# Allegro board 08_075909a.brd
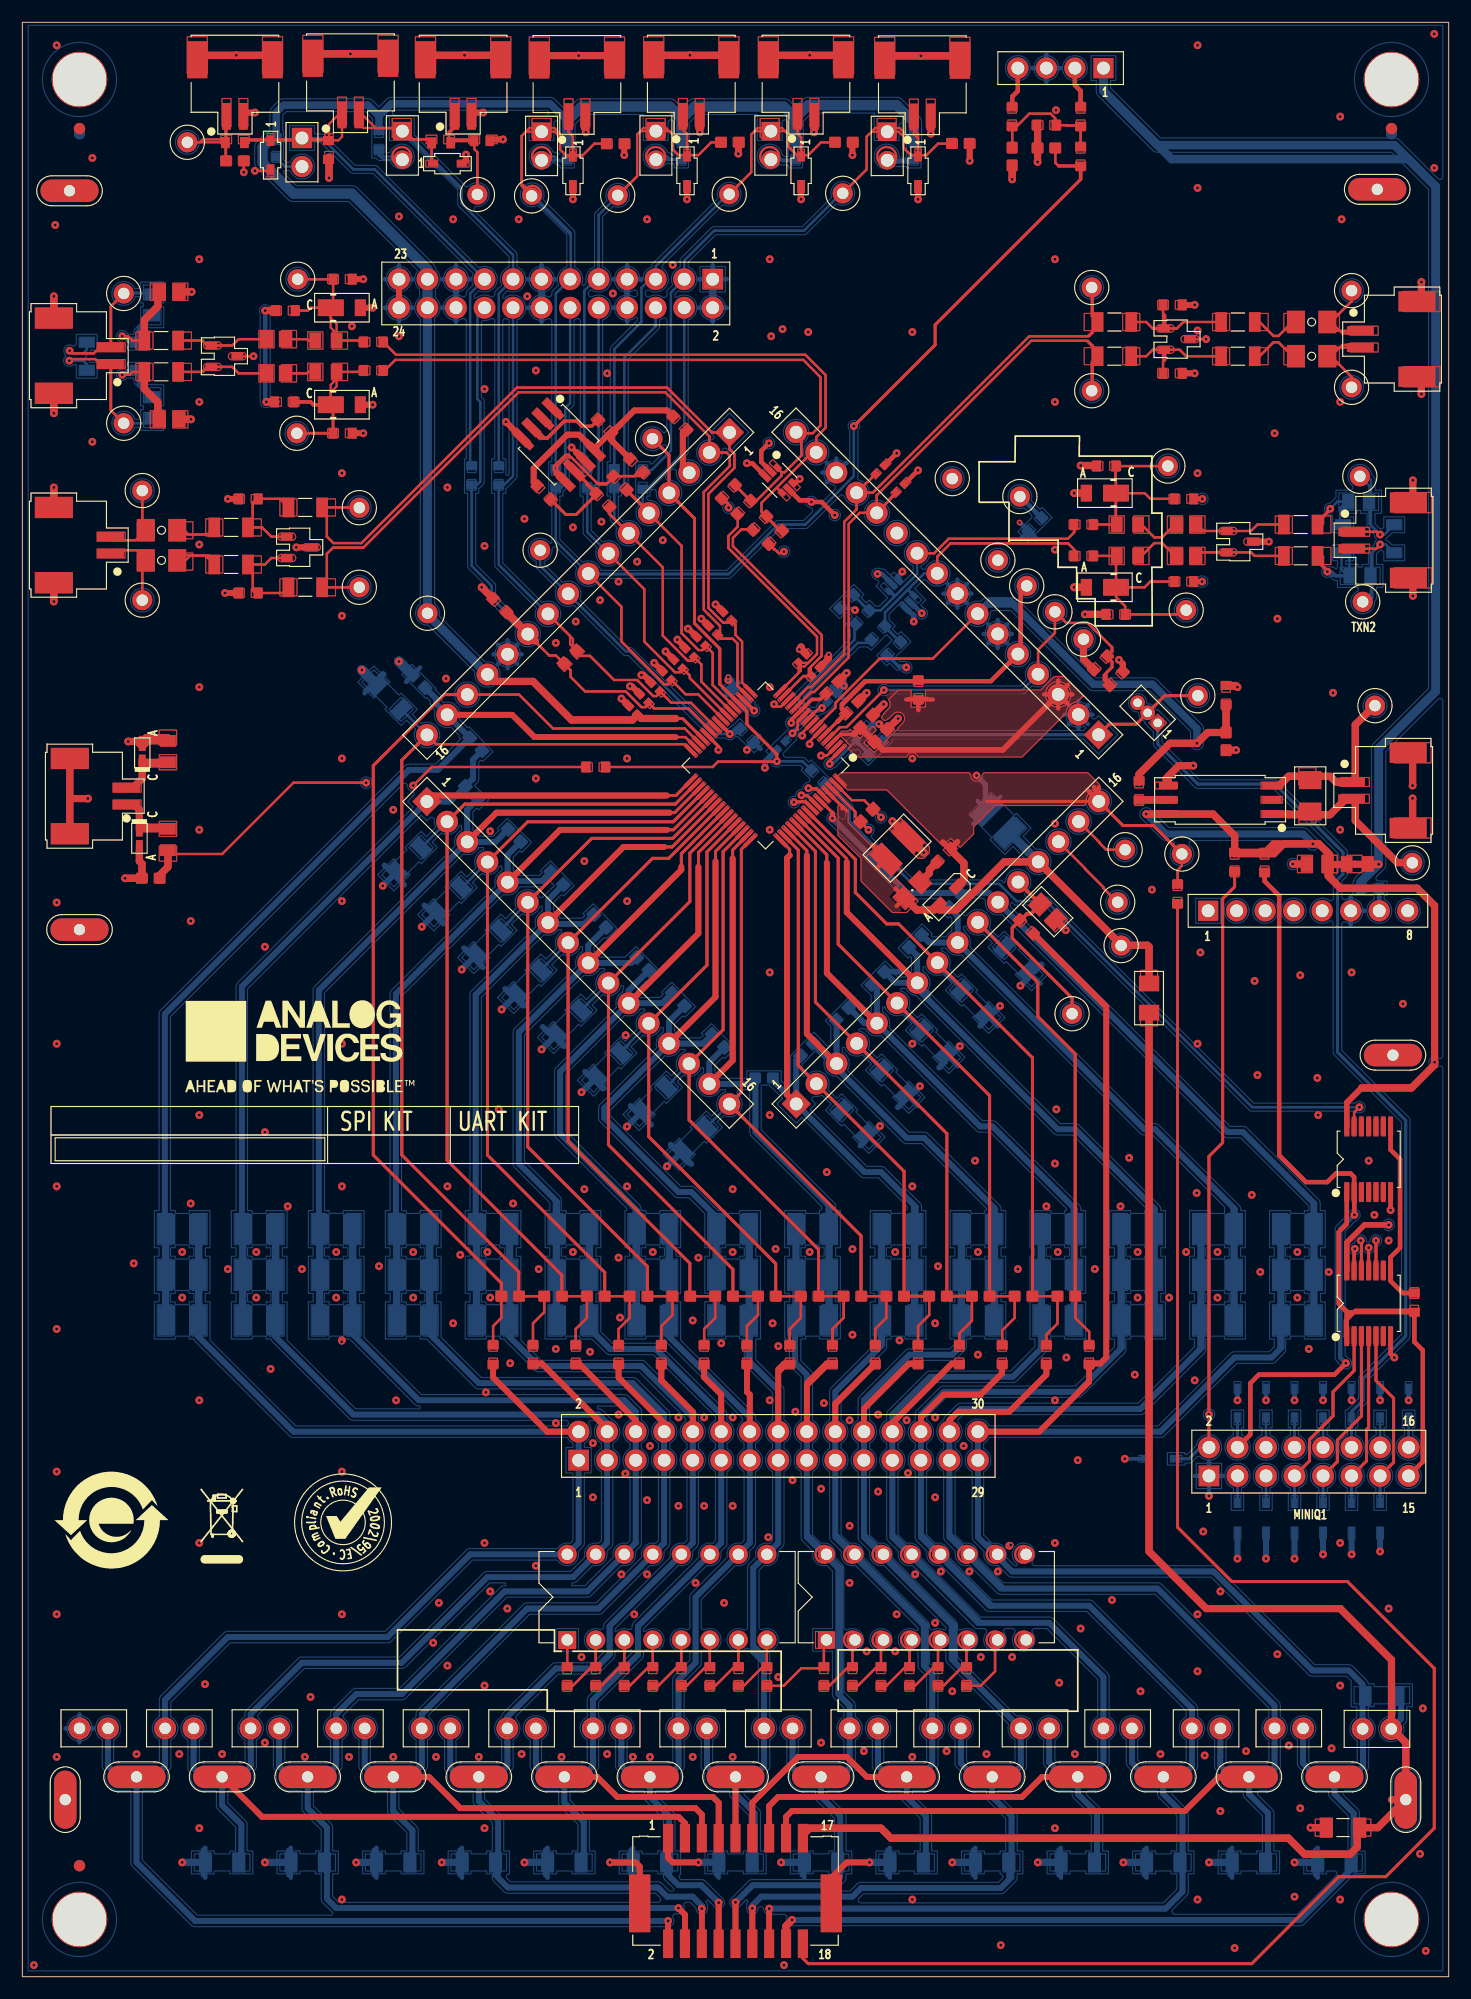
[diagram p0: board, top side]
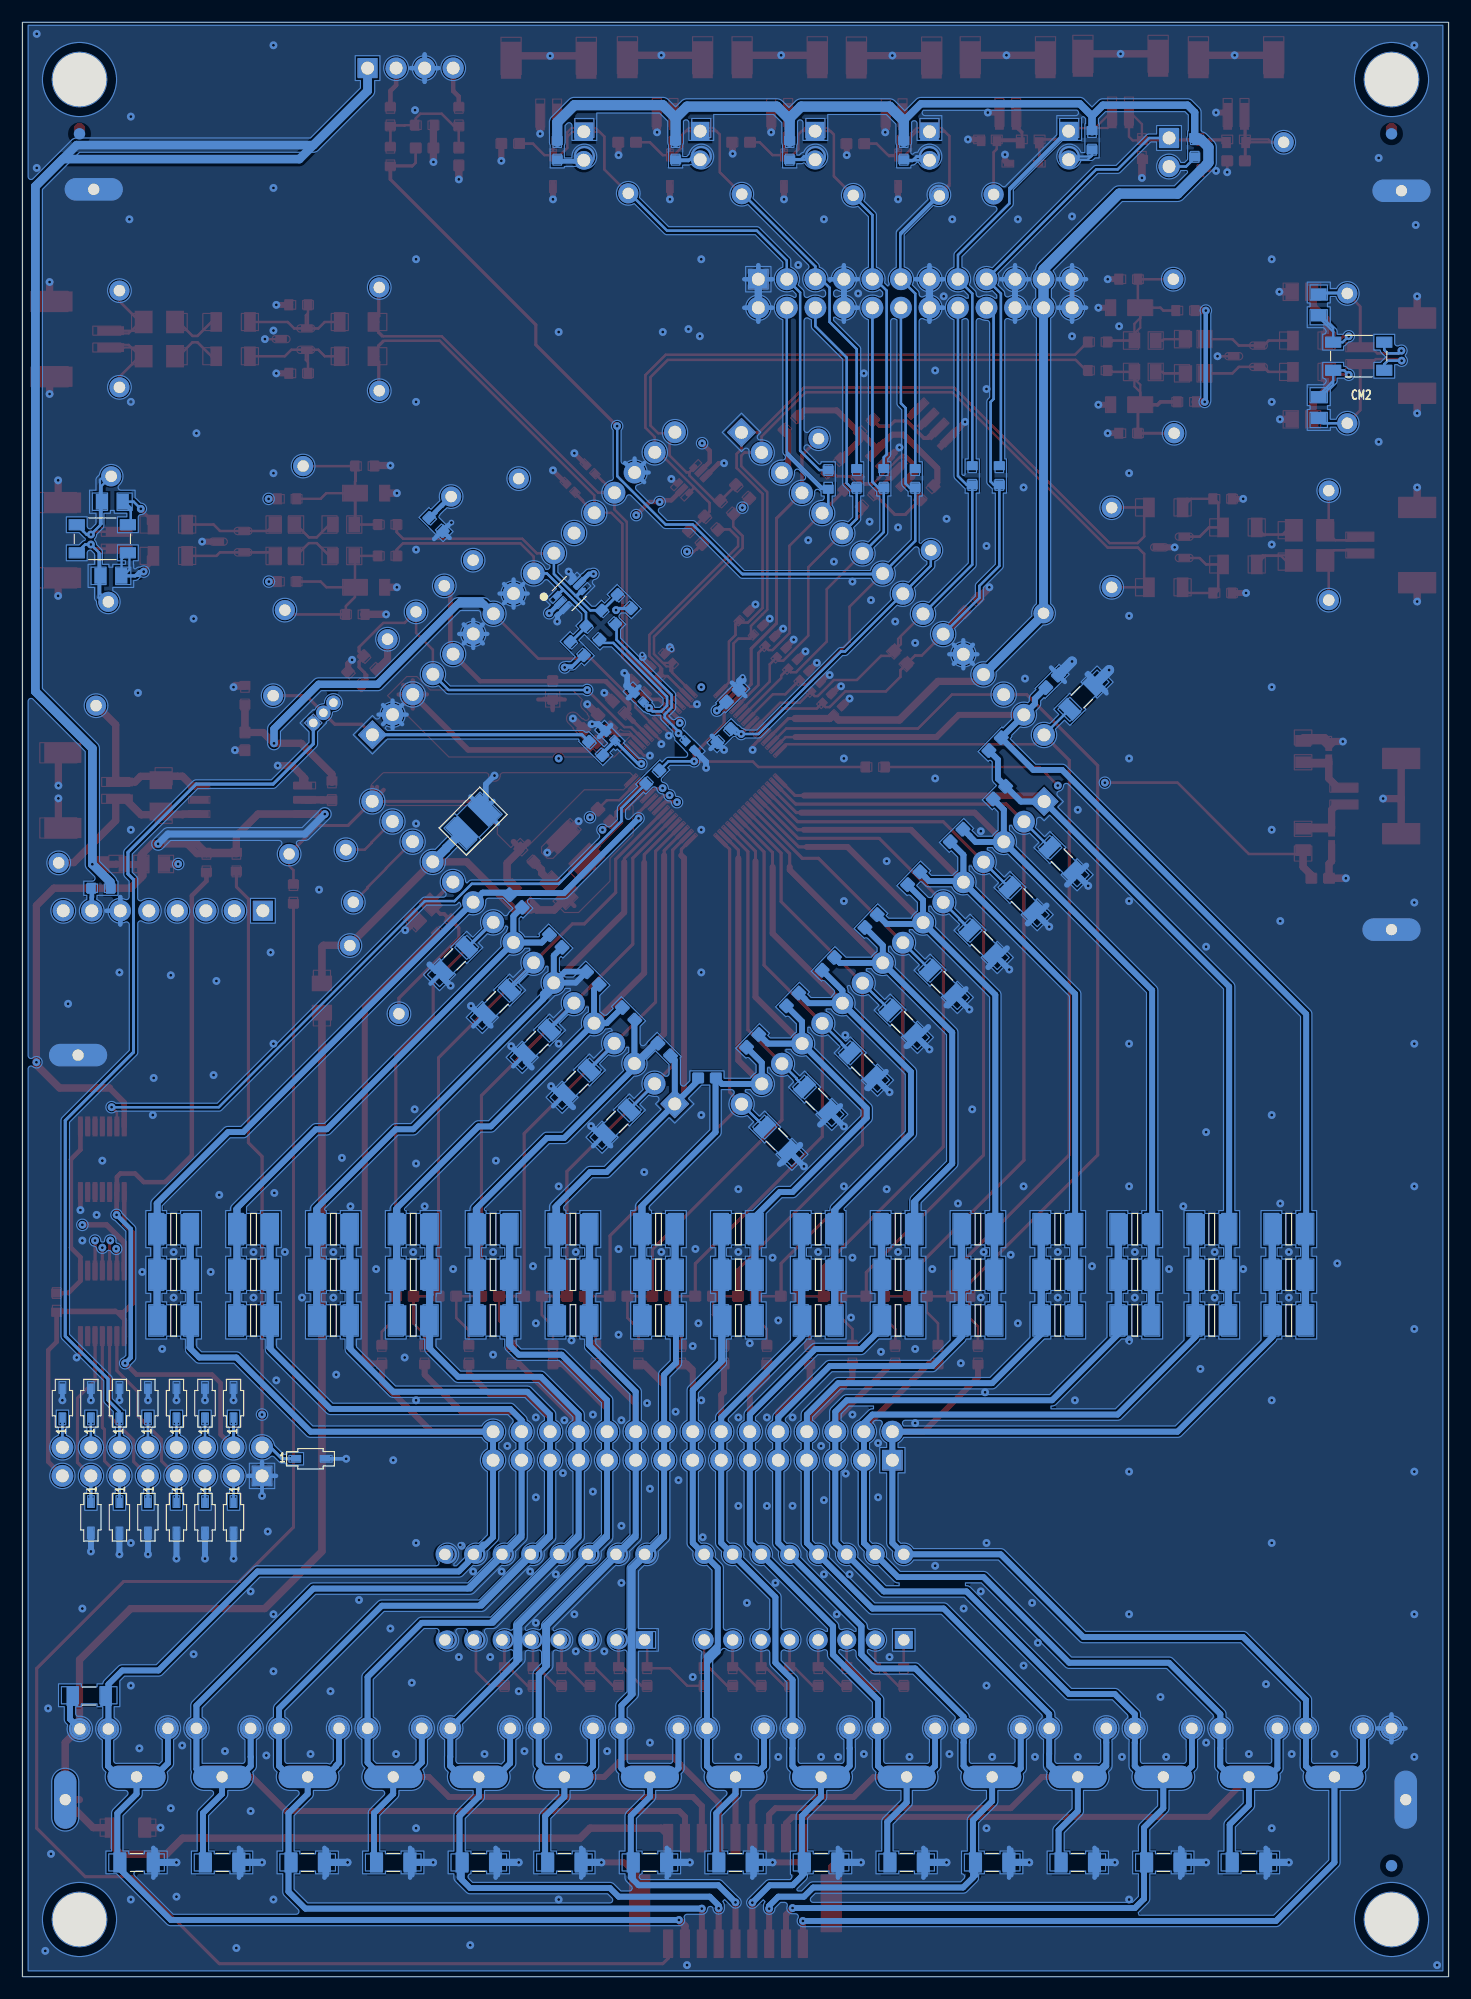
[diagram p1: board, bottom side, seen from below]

Outline 127 x 173.99 mm; copper layers: TOP, L2_GND, L3_GND, BOTTOM. Coordinates in mm from the lower left corner of the outline.
Outline path: 0,173.99 0,0 127,0 127,173.99 0,173.99

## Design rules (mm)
constraint set DEFAULT: min track width 0.203

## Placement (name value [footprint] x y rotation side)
ALARM_IN_UP  502584-0270  [CNMOLEX502584-0270]  122.15 105.61 270 top
ALARM_OUT_LP  502584-0270  [CNMOLEX502584-0270]  5.47 105.1 90 top
ALERTIN  RED  [CNKEY5001TP]  86.87 126.11 0 top
ALERTIN_N  RED  [CNKEY5001TP]  120.45 113.16 0 top
ALERTIN_P  RED  [CNKEY5001TP]  123.77 99.16 0 top
ALERTOUT  RED  [CNKEY5001TP]  56.11 136.93 0 top
AUXGND  YEL  [CNKEY5001TP]  46.1 127 0 top
B0P-  PEC02SAAN  [CNSULLINSPEC02SAAN]  5.08 22.1 0 top
B1B0  PEC02SAAN  [CNSULLINSPEC02SAAN]  12.7 22.1 0 top
B2B1  PEC02SAAN  [CNSULLINSPEC02SAAN]  20.32 22.1 0 top
B3B2  PEC02SAAN  [CNSULLINSPEC02SAAN]  27.94 22.1 0 top
B4B3  PEC02SAAN  [CNSULLINSPEC02SAAN]  35.56 22.1 0 top
B5B4  PEC02SAAN  [CNSULLINSPEC02SAAN]  43.18 22.1 0 top
B6B5  PEC02SAAN  [CNSULLINSPEC02SAAN]  50.8 22.1 0 top
B7B6  PEC02SAAN  [CNSULLINSPEC02SAAN]  58.42 22.1 0 top
B8B7  PEC02SAAN  [CNSULLINSPEC02SAAN]  66.04 22.1 0 top
B9B8  PEC02SAAN  [CNSULLINSPEC02SAAN]  73.66 22.1 0 top
B10B9  PEC02SAAN  [CNSULLINSPEC02SAAN]  81.03 22.1 0 top
B11B10  PEC02SAAN  [CNSULLINSPEC02SAAN]  88.9 22.1 0 top
B12B11  PEC02SAAN  [CNSULLINSPEC02SAAN]  96.27 22.1 0 top
B13B12  PEC02SAAN  [CNSULLINSPEC02SAAN]  104.14 22.1 0 top
B14B13  PEC02SAAN  [CNSULLINSPEC02SAAN]  111.51 22.1 0 top
BAT0  9020  [CNWEICO9020]  10.16 17.78 0 top
BAT1  9020  [CNWEICO9020]  17.78 17.78 0 top
BAT2  9020  [CNWEICO9020]  25.4 17.78 0 top
BAT3  9020  [CNWEICO9020]  33.02 17.78 0 top
BAT4  9020  [CNWEICO9020]  40.64 17.78 0 top
BAT5  9020  [CNWEICO9020]  48.26 17.78 0 top
BAT6  9020  [CNWEICO9020]  55.88 17.78 0 top
BAT7  9020  [CNWEICO9020]  63.5 17.78 0 top
BAT8  9020  [CNWEICO9020]  71.12 17.78 0 top
BAT9  9020  [CNWEICO9020]  78.74 17.78 0 top
BAT10  9020  [CNWEICO9020]  86.36 17.78 0 top
BAT11  9020  [CNWEICO9020]  93.98 17.78 0 top
BAT12  9020  [CNWEICO9020]  101.6 17.78 0 top
BAT13  9020  [CNWEICO9020]  109.22 17.78 0 top
BAT14  9020  [CNWEICO9020]  116.84 17.78 0 top
C1  0.1UF  [C0603#2]  75.18 103.38 45 top
C2  1000pF  [C0402]  74.6 110.41 45 bottom
C3  1UF  [C0603#2]  75.18 111.75 45 top
C4  0.47uF  [C0603]  73.85 112.97 45 top
C5  0.47uF  [C0603]  72.07 114.75 45 top
C6  4.7uF  [C0805H60]  79.25 96.72 45 top
C7  0.47uF  [C0603#2]  63.75 114.05 135 bottom
C8  0.01uF  [C0402]  60.45 118.87 135 top
C9  0.01uF  [C0402]  59.44 117.86 135 top
C10  0.01uF  [C0402]  58.42 116.84 135 top
C11  0.01uF  [C0402]  57.4 115.82 135 top
C12  0.01uF  [C0402]  56.39 114.81 135 top
C13  0.01uF  [C0402]  55.37 113.79 135 top
C14  100pF  [C0402]  54.43 112.7 135 top
C15  3900pF  [C0603#2]  76.45 110.48 45 top
C16  0.47uF  [C0603#2]  91.19 162.81 180 top
C17  0.01uF  [C0603#2]  88.14 162.05 270 top
C18  2.2UF  [C1210H95]  77.89 100.47 45 top
C19  2.2UF  [C1210H95]  86.87 102.87 135 bottom
C20  0.1uF  [C1206]  88.49 90.58 315 bottom
C21  0.47uF  [C0805H53]  91.3 94.82 315 top
C22  0.1uF  [C1206]  84.68 86.77 315 bottom
C23  0.1uF  [C1206]  81.13 83.21 315 bottom
C24  0.1uF  [C1206]  77.57 79.65 315 bottom
C25  0.1uF  [C1206]  74.02 76.1 315 bottom
C26  0.1uF  [C1206]  59.84 74.57 225 bottom
C27  0.1uF  [C1206]  56.29 78.13 225 bottom
C28  0.1uF  [C1206]  52.22 81.18 225 bottom
C29  0.1uF  [C1206]  48.67 84.99 225 bottom
C30  0.1uF  [C1206]  45.11 88.54 225 bottom
C31  0.1uF  [C1206]  41.55 92.1 225 bottom
C32  0.1uF  [C1206]  38 95.91 225 bottom
C33  0.1uF  [C1206]  34.44 99.47 225 bottom
C34  0.1uF  [C1206]  116.84 10.16 0 bottom
C35  0.1uF  [C1206]  109.22 10.16 0 bottom
C36  0.1uF  [C1206]  101.6 10.16 0 bottom
C37  0.1uF  [C1206]  93.98 10.16 0 bottom
C38  0.1uF  [C1206]  86.36 10.16 0 bottom
C39  0.1uF  [C1206]  78.74 10.16 0 bottom
C40  0.1uF  [C1206]  71.12 10.16 0 bottom
C41  0.1uF  [C1206]  63.5 10.16 0 bottom
C42  0.1uF  [C1206]  55.88 10.16 0 bottom
C43  0.1uF  [C1206]  48.26 10.16 0 bottom
C44  0.1uF  [C1206]  40.64 10.16 0 bottom
C45  0.1uF  [C1206]  33.02 10.16 0 bottom
C46  0.1uF  [C1206]  25.4 10.16 0 bottom
C47  0.1uF  [C1206]  17.78 10.16 0 bottom
C48  0.1uF  [C0603#2]  92.98 60.58 180 top
C49  0.1uF  [C0603#2]  89.14 60.58 180 top
C50  0.1uF  [C0603#2]  85.33 60.58 180 top
C51  0.1uF  [C0603#2]  81.52 60.58 180 top
C52  0.1uF  [C0603#2]  77.71 60.58 180 top
C53  0.1uF  [C0603#2]  73.93 60.58 180 top
C54  0.1uF  [C0603#2]  70.12 60.58 180 top
C55  0.1uF  [C0603#2]  66.31 60.58 180 top
C56  0.1uF  [C0603#2]  62.5 60.58 180 top
C57  0.1uF  [C0603#2]  58.69 60.58 180 top
C58  0.1uF  [C0603#2]  54.88 60.58 180 top
C59  0.1uF  [C0603#2]  51.07 60.58 180 top
C60  0.1uF  [C0603#2]  47.26 60.58 180 top
C61  0.1uF  [C0603#2]  43.43 60.58 180 top
C62  0.1uF  [C0603#2]  83.07 95.77 225 bottom
C63  0.1uF  [C0603#2]  79.51 92.21 225 bottom
C64  0.1uF  [C0603#2]  76.21 88.91 225 bottom
C65  0.1uF  [C0603#2]  73.02 85.72 225 bottom
C66  0.1uF  [C0603#2]  69.84 82.54 225.1 bottom
C67  0.1uF  [C0603#2]  66.03 80.01 180 bottom
C68  0.1uF  [C0603#2]  61.97 83.32 133.8 bottom
C69  0.1uF  [C0603#2]  58.41 87 134 bottom
C70  0.1uF  [C0603#2]  55.24 90.18 133.9 bottom
C71  0.1uF  [C0603#2]  51.43 93.99 133.7 bottom
C72  0.1uF  [C0603#2]  47.62 97.8 133.8 bottom
C73  0.1uF  [C0603#2]  43.81 101.61 135.4 bottom
C74  0.1uF  [C0603#2]  40 105.42 134.8 bottom
C75  0.1uF  [C0603#2]  40.38 109.74 134 bottom
C76  15pF  [C0402]  72.06 113.84 45 bottom
C77  18pF  [C0402]  78.15 132.51 45 top
C78  15pF  [C0402]  70.63 116.15 45 top
C79  15pF  [C0402]  67.56 109.6 225 bottom
C80  18pF  [C0402]  61.55 119.81 135 top
C81  18pF  [C0402]  76.38 134.16 45 top
C82  15pF  [C0402]  69.47 117.35 45 top
C83  18pF  [C0402]  62.82 121.08 135 top
C84  0.1uF  [C1206]  32.66 113.89 135 bottom
C85  1UF  [C0603#2]  35.3 115.32 135 bottom
C86  0.01uF  [C0603#2]  48.77 117.49 225 top
C87  39PF  [C0603#2]  107.19 109.97 270 top
C88  100pF  [C1206H37]  114.68 105.13 270 top
C89  2200PF  [C1206H71]  12.38 126.09 0 top
C90  2200PF  [C1206H71]  12.38 128.78 0 top
C91  2200PF  [C1206H71]  114.81 144.27 0 top
C92  2200PF  [C1206H71]  114.81 147.32 0 top
C93  15pF  [C0603#2]  11.42 97.79 180 top
C100  0.1uF  [C1206]  117.6 13.26 180 top
C101  100pF  [C0805]  13.06 138.65 0 top
C102  100pF  [C0805]  13.06 150.01 180 top
C104  0.01uF  [C0603#2]  18.92 161.67 0 top
C105  0.01uF  [C0603#2]  52.81 163.19 0 top
C106  0.01uF  [C0603#2]  83.54 163.22 0 top
C107  0.01uF  [C0603#2]  73.15 163.32 0 top
C108  0.01uF  [C0603#2]  63.02 163.32 0 top
C109  0.01uF  [C0603]  40.92 163.42 0 top
CM1  2800 OHMS  [FL1812]  119.89 128.02 180 bottom
CM2  2800 OHMS  [FL1812]  8 144.28 0 bottom
CPN  RED  [CNKEY5001TP]  97.54 95.66 0 top
CPP  RED  [CNKEY5001TP]  98.2 100.33 0 top
CURRENTSENSE  502584-0270  [CNMOLEX502584-0270]  29.21 169.54 0 top
D3  SP4021-01FTG  [SOD323_B]  22.1 162.18 270 top
D4  SP4021-01FTG  [SOD323_B]  37.85 161.42 0 top
D5  SP4021-01FTG  [SOD323_B]  79.76 160.78 270 top
D6  SP4021-01FTG  [SOD323_B]  69.34 160.78 270 top
D7  SP4021-01FTG  [SOD323_B]  59.18 160.78 270 top
D8  SP4021-01FTG  [SOD323_B]  49.02 160.78 270 top
D9  PESD3V3U1UB,115  [SOD523H26]  10.41 101.35 270 top
D10  PESD3V3U1UB,115  [SOD523H26]  10.67 108.97 90 top
D11  SP4021-01FTG  [SOD323_B]  120.9 40.89 270 bottom
D12  SP4021-01FTG  [SOD323_B]  118.36 40.89 270 bottom
D13  SP4021-01FTG  [SOD323_B]  115.82 40.89 270 bottom
D14  SP4021-01FTG  [SOD323_B]  113.28 40.89 270 bottom
D15  SP4021-01FTG  [SOD323_B]  110.74 40.89 270 bottom
D16  SP4021-01FTG  [SOD323_B]  108.2 40.89 270 bottom
D18  SP4021-01FTG  [SOD323_B]  123.44 51.05 90 bottom
D19  SP4021-01FTG  [SOD323_B]  120.9 51.05 90 bottom
D20  SP4021-01FTG  [SOD323_B]  118.36 51.05 90 bottom
D21  SP4021-01FTG  [SOD323_B]  115.82 51.05 90 bottom
D22  SP4021-01FTG  [SOD323_B]  113.28 51.05 90 bottom
D23  SP4021-01FTG  [SOD323_B]  110.74 51.05 90 bottom
D24  SP4021-01FTG  [SOD323_B]  108.2 51.05 90 bottom
D25  SP4021-01FTG  [SOD323_B]  101.35 46.1 180 bottom
D26  DFLS1100-7  [POWERDI123]  96.39 132.08 180 top
D28  DFLS1100-7  [POWERDI123]  28.45 148.59 0 top
D29  SESDONCAN1LT1G  [SOT23_B]  102.82 145.8 270 top
D30  DFLS1100-7  [POWERDI123]  96.39 123.7 180 top
D31  DFLS1100-7  [POWERDI123]  28.45 139.95 0 top
D32  SESDONCAN1LT1G  [SOT23_B]  24.69 127.26 270 top
D33  SESDONCAN1LT1G  [SOT23_B]  108.41 127.76 270 top
D34  SESDONCAN1LT1G  [SOT23_B]  17.98 144.27 270 top
D40  BAT20J  [SOD323]  82.42 96.24 225 top
DCIN  RED  [CNKEY5001TP]  97.84 91.8 0 top
GND_A  9020  [CNWEICO9020]  5.08 93.22 0 top
GND_A1  9020  [CNWEICO9020]  122.05 82.04 0 top
GND_A2  9020  [CNWEICO9020]  4.19 159 0 top
GND_A3  9020  [CNWEICO9020]  120.65 159.13 0 top
GP/AUX0  BLK  [CNKEY5001TP]  73.05 158.78 0 top
GP/AUX1  BLK  [CNKEY5001TP]  62.94 158.7 0 top
GP/AUX2  BLK  [CNKEY5001TP]  53.01 158.6 0 top
GP/AUX3  BLK  [CNKEY5001TP]  45.34 158.55 0 top
GP/AUX4  BLK  [CNKEY5001TP]  40.51 158.67 0 top
GP/AUX5  BLK  [CNKEY5001TP]  14.68 163.32 0 top
GPIO_AUX0  502584-0270  [CNMOLEX502584-0270]  80.14 169.37 0 top
GPIO_AUX1  502584-0270  [CNMOLEX502584-0270]  69.77 169.42 0 top
GPIO_AUX2  502584-0270  [CNMOLEX502584-0270]  59.56 169.42 0 top
GPIO_AUX3  502584-0270  [CNMOLEX502584-0270]  49.38 169.39 0 top
GPIO_AUX4  502584-0270  [CNMOLEX502584-0270]  39.24 169.42 0 top
GPIO_AUX5  502584-0270  [CNMOLEX502584-0270]  18.92 169.42 0 top
HV  RED  [CNKEY5001TP]  103.25 99.95 0 top
J1  TSW-116-07-G-S  [CNHDR1X16H335]  95.83 110.57 135 top
J2  TSW-116-07-G-S  [CNHDR1X16H335]  62.97 137.49 225 top
J3  TSW-116-07-G-S  [CNHDR1X16H335]  36.02 104.62 315 top
J4  TSW-116-07-G-S  [CNHDR1X16H335]  68.91 77.7 45 top
J5  PEC12DAAN  [CNTHMHDR2X12L1200W200H343]  61.47 151.13 180 top
J6  PBC15DAAN  [CNTHMHDR2X15L1500W200H330]  49.53 45.97 0 top
J7  5031541890  [CNMOLEX5031541890]  63.5 7.62 180 top
J8  SSW-104-01-G-S  [CNSAMTECSSW-104-XX-X-S]  96.27 169.93 180 top
L1  600OHM AT 100MEGHZ  [L0805]  103.63 126.49 180 top
L2  600OHM AT 100MEGHZ  [L0805]  103.63 129.29 180 top
L3  600OHM AT 100MEGHZ  [L0805]  22.58 142.75 0 top
L4  600OHM AT 100MEGHZ  [L0805]  22.58 145.8 0 top
MINIQ1  PEC08DAAN  [CNTHMHDR2X8L800W200H343_OE]  105.66 44.58 0 top
MINIQ2  SSW-108-01-G-S  [CNSAMTECSSW-108-01-G-S]  105.59 94.89 0 top
NOREF  -  []  24.13 82.8 0 top
NOREF#2  -  []  64.49 194.18 0 top
NOREF#3  -  []  127 0 90 top
NOREF#4  -  [unnamed#2]  5.08 9.87 0 top
NOREF#5  -  []  -181.84 -111.94 0 top
NOREF#6  -  []  215.65 186.06 0 top
NOREF#7  -  []  28.55 40.44 0 top
NOREF#8  -  []  127 173.99 180 top
NOREF#9  -  []  2.67 21.89 0 top
NOREF#10  -  []  0 173.99 270 top
NOREF#11  -  []  0 173.99 0 top
NOREF#12  -  []  127 0 0 top
NOREF#13  -  []  127 0 90 top
NOREF#14  -  []  2.54 74.42 0 top
NOREF#15  -  []  0 0 0 top
NOREF#16  -  []  0 173.99 0 top
NOREF#17  -  [unnamed#2]  121.92 164.54 0 top
NOREF#18  -  []  0 0 0 top
NOREF#19  -  []  -74.4 -30.86 0 top
NOREF#20  -  []  0 0 0 top
NOREF#21  -  []  91.64 33.95 0 top
NOREF#22  -  []  -183.21 -111.58 0 top
NOREF#23  -  []  0 0 0 top
NOREF#24  -  []  146.91 316.51 0 top
NOREF#25  -  []  124.3 169.11 0 top
NOREF#26  -  []  0 0 0 top
NOREF#27  -  []  123.72 22 0 top
NOREF#28  -  [unnamed#2]  5.08 164.54 0 top
NOREF#29  -  []  17.55 36.83 0 top
NOREF#30  -  []  7.92 40.64 0 top
NOREF#31  -  [unnamed#2]  5.08 9.87 180 bottom
NOREF#32  -  [unnamed#2]  121.92 5.08 180 bottom
NOREF#33  -  [unnamed#2]  5.08 164.08 180 bottom
NOREF#34  -  [unnamed#2]  121.92 164.08 180 bottom
NOREF#35  -  [unnamed#2]  5.08 168.91 180 bottom
NOREF#36  -  [unnamed#2]  5.08 5.08 180 bottom
NOREF#37  -  [unnamed#2]  121.92 168.91 180 bottom
OPTO_OUT  YEL  [CNKEY5001TP]  88.82 131.78 0 top
P+B14  PEC02SAAN  [CNSULLINSPEC02SAAN]  119.35 22.05 0 top
PACK+  9020  [CNWEICO9020]  123.19 15.75 90 top
PACK-  9020  [CNWEICO9020]  3.81 15.75 90 top
Q1  BC857BS-7-F  [SOT363-3]  67.44 133.22 225 top
Q2  BC857BS-7-F  [SOT363-3]  78.31 123.14 225 bottom
R1  0  [R0603]  73.41 122.43 45 bottom
R2  0  [R0603]  62.87 132.21 45 top
R3  0  [R0603]  77.6 118.24 45 bottom
R4  0  [R0603]  67.06 128.14 45 top
R5  0  [R0603]  76.2 119.63 225 bottom
R6  0  [R0603]  74.8 121.03 225 bottom
R7  0  [R0603]  65.66 129.41 225 top
R8  0  [R0603]  64.26 130.81 225 top
R9  10K  [R0603]  96.01 116.97 225 top
R10  10K  [R0603]  97.41 115.57 225 top
R11  0  [R0603]  79.78 114.55 90 top
R12  100K  [R0603]  90.17 129.29 45 bottom
R13  0  [R0603]  94.49 129.29 180 top
R14  0  [R0603]  31.24 143 0 top
R15  0  [R0603]  94.49 126.49 180 top
R16  0  [R0603]  31.24 145.54 0 top
R17  100  [R1206-2]  100.33 87.12 90 top
R18  1.02K  [R0603]  89.41 93.47 135 top
R19  10  [R0603]  82.09 99.87 45 top
R20  0  [R0805]  11.56 139.7 90 bottom
R21  22  [R1210]  113.54 62.48 0 bottom
R22  100K  [R0603]  75.95 109.35 45 bottom
R23  0  [R0603]  102.87 96.39 90 top
R24  0  [R0603]  120.02 96.9 180 bottom
R25  22  [R1210]  106.43 66.55 0 bottom
R26  0  [R0603]  58.55 138.3 315 top
R27  0  [R0805]  11.56 148.84 270 bottom
R28  0  [R0603]  64.52 110.49 315 bottom
R29  22  [R1210]  99.31 66.55 0 bottom
R30  0  [R0603]  42.5 122.09 315 top
R31  0  [R0603]  27.25 162.64 270 top
R32  0  [R0805]  115.32 99.06 0 top
R33  22  [R1210]  92.2 66.55 0 bottom
R34  0  [R0805]  118.87 99.06 0 top
R35  22  [R1210]  113.54 66.55 0 bottom
R36  22  [R1210]  106.43 62.48 0 bottom
R37  22  [R1210]  85.09 66.55 0 bottom
R38  22  [R1210]  99.31 62.48 0 bottom
R39  22  [R1210]  92.2 62.48 0 bottom
R40  22  [R1210]  85.09 62.48 0 bottom
R41  22  [R1210]  77.98 66.55 0 bottom
R42  22  [R1210]  77.98 62.48 0 bottom
R43  22  [R1210]  70.36 66.55 0 bottom
R44  22  [R1210]  63.25 66.55 180 bottom
R45  22  [R1210]  70.36 62.48 0 bottom
R46  22  [R1210]  56.13 66.55 180 bottom
R47  22  [R1210]  49.02 66.55 180 bottom
R48  22  [R1210]  41.91 66.55 180 bottom
R49  22  [R1210]  63.25 62.48 180 bottom
R50  22  [R1210]  34.8 66.55 180 bottom
R51  22  [R1210]  27.94 66.55 180 bottom
R52  22  [R1210]  21.08 66.55 180 bottom
R53  22  [R1210]  56.13 62.48 180 bottom
R54  22  [R1210]  14.22 62.48 180 bottom
R55  22  [R1210]  99.31 58.42 0 bottom
R56  22  [R1210]  113.54 58.42 0 bottom
R57  22  [R1210]  49.02 62.48 180 bottom
R58  22  [R1210]  106.43 58.42 0 bottom
R59  22  [R1210]  92.2 58.42 0 bottom
R60  22  [R1210]  85.09 58.42 0 bottom
R61  22  [R1210]  41.91 62.48 180 bottom
R62  22  [R1210]  70.36 58.42 0 bottom
R63  22  [R1210]  63.25 58.42 180 bottom
R64  22  [R1210]  49.02 58.42 180 bottom
R65  22  [R1210]  34.8 62.48 180 bottom
R66  22  [R1210]  41.91 58.42 180 bottom
R67  22  [R1210]  34.8 58.42 180 bottom
R68  22  [R1210]  27.94 58.42 180 bottom
R69  22  [R1210]  27.94 62.48 180 bottom
R70  22  [R1210]  21.08 58.42 180 bottom
R71  22  [R1210]  77.98 58.42 0 bottom
R72  22  [R1210]  56.13 58.42 180 bottom
R73  22  [R1210]  21.08 62.48 180 bottom
R74  22  [R1210]  14.22 58.42 180 bottom
R77  22  [R1210]  14.22 66.55 180 bottom
R81  1K  [R0603]  49.28 55.37 90 top
R82  1K  [R0603]  45.47 55.37 90 top
R83  1K  [R0603]  41.91 55.37 90 top
R84  1K  [R0603]  64.52 55.37 90 top
R85  1K  [R0603]  60.71 55.37 90 top
R86  1K  [R0603]  56.9 55.37 90 top
R87  1K  [R0603]  53.09 55.37 90 top
R88  1K  [R0603]  72.14 55.37 90 top
R89  1K  [R0603]  68.33 55.37 90 top
R90  1K  [R0603]  75.95 55.37 90 top
R91  1K  [R0603]  95 55.37 90 top
R92  1K  [R0603]  91.19 55.37 90 top
R93  1K  [R0603]  87.25 55.37 90 top
R94  1K  [R0603]  83.44 55.37 90 top
R95  1K  [R0603]  79.76 55.37 90 top
R96  2K  [R0603]  84.07 26.73 90 top
R97  2K  [R0603]  81.53 26.73 90 top
R98  2K  [R0603]  78.99 26.73 90 top
R99  2K  [R0603]  76.45 26.73 90 top
R100  2K  [R0603]  73.91 26.73 90 top
R101  2K  [R0603]  71.37 26.73 90 top
R102  2K  [R0603]  66.29 26.73 90 top
R103  2K  [R0603]  63.75 26.73 90 top
R104  2K  [R0603]  61.21 26.73 90 top
R105  2K  [R0603]  58.67 26.73 90 top
R106  2K  [R0603]  56.13 26.73 90 top
R107  2K  [R0603]  53.59 26.73 90 top
R108  2K  [R0603]  51.05 26.73 90 top
R109  2K  [R0603]  48.51 26.73 90 top
R110  100K  [R0603]  107.19 114.11 90 top
R111  360  [R0805]  12.95 101.24 270 top
R112  360  [R0805]  12.95 109.07 90 top
R113  1K  [R0603]  99.44 105.6 90 top
R114  10K  [R0603]  107.95 99.25 270 top
R115  10K  [R0603]  46.44 132.12 315 top
R116  1K  [R0603]  55.24 133.29 270 bottom
R117  1K  [R0603]  52.7 133.41 270 bottom
R118  1K  [R0603]  47.5 133.41 270 bottom
R119  1K  [R0603]  42.42 133.67 270 bottom
R120  1K  [R0603]  40.01 133.67 270 bottom
R121  1K  [R0603]  50.29 133.41 270 bottom
R122  10K  [R0603]  79.38 162.62 270 bottom
R123  10K  [R0603]  68.83 162.62 270 bottom
R124  10K  [R0603]  58.67 162.62 270 bottom
R125  10K  [R0603]  51.86 138 135 top
R126  10K  [R0603]  48.51 162.62 270 bottom
R127  10K  [R0603]  31.75 163.51 270 bottom
R128  10K  [R0603]  22.61 162.88 270 bottom
R129  0  [R1206]  97.24 144.27 180 top
R130  0  [R1206]  97.24 147.32 180 top
R131  10K  [R0603]  54.69 134.54 315 top
R132  10K  [R0603]  123.95 60.01 90 top
R133  10K  [R0603]  103.44 124.21 180 top
R134  10K  [R0603]  97.35 121.28 180 top
R136  0  [R0603]  51.05 107.7 0 top
R137  15K  [R0603]  94.23 162.05 90 top
R138  0  [R1206]  25.19 123.7 0 top
R139  15K  [R0603]  91.19 164.85 180 top
R140  0  [R1206]  25.19 130.81 0 top
R141  0  [R0603]  70.87 106.81 315 bottom
R142  10K  [R0603]  110.62 99.19 270 top
R143  0  [R0603]  51.69 131.44 135 top
R144  0  [R0603]  94.23 165.61 90 top
R145  0  [R0603]  88.14 165.61 90 top
R146  10K  [R0603]  103.44 131.57 180 top
R147  10K  [R0603]  96.52 134.49 180 top
R148  0  [R0603]  53.21 132.97 315 top
R150  10K  [R0603]  28.51 137.41 0 top
R151  10K  [R0603]  23.31 140.21 0 top
R152  10K  [R0603]  28.51 151.13 0 top
R154  10K  [R0603]  23.43 148.34 0 top
R155  100K  [R0603]  102.42 142.75 0 top
R157  49.9  [R0805]  27.03 142.88 0 top
R158  49.9  [R0805]  98.4 126.49 180 top
R159  49.9  [R0805]  98.4 129.29 180 top
R160  49.9  [R0805]  27.03 145.67 0 top
R161  100K  [R0603]  102.42 148.84 0 top
R162  1.5K  [R1206]  108.24 144.27 180 top
R164  1.5K  [R1206]  108.24 147.32 180 top
R168  100K  [R0603]  20.13 123.19 180 top
R169  100K  [R0603]  20.13 131.57 180 top
R172  1.5K  [R1206]  18.58 125.73 0 top
R173  1.5K  [R1206]  18.58 129.03 0 top
R179  0  [R1206]  113.83 126.49 180 top
R180  0  [R1206]  113.83 129.29 180 top
R181  0  [R1206]  12.36 142.88 0 top
R182  0  [R1206]  12.36 145.67 0 top
R183  0  [R0805]  119.13 124.71 180 bottom
R184  0  [R0805]  119 131.32 180 bottom
R185  0  [R0603]  37.29 163.27 180 top
R186  0  [R0603]  18.92 163.3 0 top
R187  0  [R1206]  121.06 24.97 180 bottom
RXLN  RED  [CNKEY5001TP]  30 123.7 0 top
RXLP  RED  [CNKEY5001TP]  30 130.78 0 top
RXLP_CONN  502584-0270  [CNMOLEX502584-0270]  4.05 127.46 90 top
RXN1  BLK  [CNKEY5001TP]  10.67 122.56 0 top
RXN2  BLK  [CNKEY5001TP]  118.36 141.5 0 top
RXP1  RED  [CNKEY5001TP]  10.67 132.31 0 top
RXP2  RED  [CNKEY5001TP]  118.36 150.11 0 top
RXUN  RED  [CNKEY5001TP]  95.22 141.2 0 top
RXUP  RED  [CNKEY5001TP]  95.22 150.39 0 top
RXUP_CONN  502584-0270  [CNMOLEX502584-0270]  122.94 145.8 270 top
SHDNL  YEL  [CNKEY5001TP]  104.67 114.05 0 top
SHDNL_SEL  FTS-103-01-F-S  [CN1X3H159]  101.1 111.62 135 top
SW1  ADE0804  [SWDIP16]  71.6 29.97 0 top
SW2  ADE0804  [SWDIP16]  48.51 29.97 0 top
THERM  YEL  [CNKEY5001TP]  36.07 121.39 0 top
THERM1  3-644456-2  [CNHDR1X2H408]  77.01 164.26 270 top
THERM2  3-644456-2  [CNHDR1X2H408]  66.65 164.31 270 top
THERM3  3-644456-2  [CNHDR1X2H408]  56.41 164.31 270 top
THERM4  3-644456-2  [CNHDR1X2H408]  46.23 164.26 270 top
THERM5  3-644456-2  [CNHDR1X2H408]  33.83 164.31 270 top
THERM6  3-644456-2  [CNHDR1X2H408]  24.89 163.7 270 top
TXLN  RED  [CNKEY5001TP]  24.43 137.41 0 top
TXLP  RED  [CNKEY5001TP]  24.51 151.13 0 top
TXLP_CONN  502584-0270  [CNMOLEX502584-0270]  4.05 144.32 90 top
TXN1  BLK  [CNKEY5001TP]  9.02 138.3 0 top
TXN2  BLK  [CNKEY5001TP]  119.35 122.4 0 top
TXP1  RED  [CNKEY5001TP]  9.02 149.86 0 top
TXP2  RED  [CNKEY5001TP]  119.1 133.58 0 top
TXUN  RED  [CNKEY5001TP]  103.63 121.67 0 top
TXUP  RED  [CNKEY5001TP]  102.01 134.49 0 top
TXUP_CONN  502584-0270  [CNMOLEX502584-0270]  122.17 127.89 270 top
U1  ADES1754GCB/V+  [QFP64_10X10]  66.17 107.83 135 top
U2  MAX3378EEUD+  [TSSOP14]  119.89 59.94 0 top
U3  AT24CS08-SSHM-T  [SO8]  47.75 136.4 225 top
U4  MAX3390EEUD+  [TSSOP14]  119.89 72.77 0 top
U5  TLP2770(TP,E  [SO6_3_84X7_5]  106.66 104.78 90 top
UARTSEL  RED  [CNKEY5001TP]  91.95 121.51 0 top
VAA  RED  [CNKEY5001TP]  94.49 119.08 0 top
VBLK  RED  [CNKEY5001TP]  93.47 85.72 0 top
VDDL1  YEL  [CNKEY5001TP]  89.43 123.83 0 top
VDDL2/3  YEL  [CNKEY5001TP]  82.8 133.38 0 top

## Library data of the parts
ALARM_IN_UP ALARM_OUT_LP CURRENTSENSE GPIO_AUX0-GPIO_AUX5 RXLP_CONN RXUP_CONN TXLP_CONN TXUP_CONN = CN2P_2GND: User Part Number: UPN; Tolerance: N/A; alternate symbols: (CNMOLEX502584-0270); part number: CN2P_2GND_SM-502584-0270,E061613,CNMOLEX502584-0270; tolerance: N/A
ALERTIN ALERTIN_N ALERTIN_P ALERTOUT CPN CPP DCIN HV RXLN RXLP RXP1 RXP2 RXUN RXUP TXLN TXLP TXP1 TXP2 TXUN TXUP UARTSEL VAA VBLK = CNTP1P: Tolerance: N/A; User Part Number: UPN; alternate symbols: (CNKEY5001TP); part number: CNTP1P_TH-RED,E016323,CNKEY5001TP; tolerance: N/A
AUXGND OPTO_OUT SHDNL THERM VDDL1 VDDL2/3 = CNTP1P: Tolerance: N/A; User Part Number: UPN; alternate symbols: (CNKEY5001TP); part number: CNTP1P_TH-YEL,E016321,CNKEY5001TP; tolerance: N/A
B0P- B1B0 B2B1 B3B2 B4B3 B5B4 B6B5 B7B6 B8B7 B9B8 B10B9 B11B10 B12B11 B13B12 B14B13 P+B14 = CN2P: Tolerance: N/A; User Part Number: UPN; alternate symbols: (CNSULLINSPEC02SAAN); part number: CN2P_TH-PEC02SAAN,E011286,CNSULLINSPEC02SAAN; tolerance: N/A
BAT0-BAT14 GND_A GND_A1-GND_A3 PACK+ PACK- = CN1P: User Part Number: UPN; Tolerance: N/A; alternate symbols: (CNWEICO9020); part number: CN1P_TH-9020,E062254,CNWEICO9020; tolerance: N/A
C1 = CAP: User Part Number: UPN; Tolerance: 10; alternate symbols: (C0603); part number: CAP_SM-0.1UF,100V,10,E048494,C0603; tolerance: 10
C2 = CAP: User Part Number: UPN; Tolerance: 10; alternate symbols: (C0402); part number: CAP_SM-1000PF,100V,10,E030277,C0402; tolerance: 10
C3 C85 = CAP: User Part Number: UPN; Tolerance: 10; alternate symbols: (C0603); part number: CAP_SM-1UF,6.3V,10,E061150,C0603; tolerance: 10
C4 C5 C7 C16 = CAP: User Part Number: UPN; Tolerance: 10; alternate symbols: (C0603); part number: CAP_SM-0.47UF,16V,10,E027925,C0603; tolerance: 10
C6 = CAP: Tolerance: 10; User Part Number: UPN; alternate symbols: (C0805H60); part number: CAP_SM-4.7UF,35V,10,E026260,C0805H60; tolerance: 10
C8-C13 = CAP: User Part Number: UPN; Tolerance: 10; alternate symbols: (C0402); part number: CAP_SM-0.01UF,16V,10,E019652,C0402; tolerance: 10
C14 = CAP: User Part Number: UPN; Tolerance: 1; alternate symbols: (C0402); part number: CAP_SM-100PF,50V,1,E033918,C0402; tolerance: 1
C15 = CAP: User Part Number: UPN; Tolerance: 5; alternate symbols: (C0603); part number: CAP_SM-3900PF,50V,5,E024825,C0603; tolerance: 5
C17 C86 C104-C109 = CAP: User Part Number: UPN; Tolerance: 10; alternate symbols: (C0603L); part number: CAP_SM-0.01UF,16V,10,E042630,C0603; tolerance: 10
C18 C19 = CAP: Tolerance: 10; User Part Number: UPN; alternate symbols: (C1210H95); part number: CAP_SM-2.2UF,100V,10,E044242,C1210H95; tolerance: 10
C20 C22-C33 C84 = CAP: User Part Number: UPN; Tolerance: 10; alternate symbols: (C1206); part number: CAP_SM-0.1UF,100V,10,E019857,C1206; tolerance: 10
C21 = CAP: Tolerance: 10; User Part Number: UPN; alternate symbols: (C0805H53); part number: CAP_SM-0.47UF,100V,10,E030331,C0805H53; tolerance: 10
C34-C47 C100 = CAP: User Part Number: UPN; Tolerance: 5; alternate symbols: (C1206); part number: CAP_SM-0.1UF,100V,5,E019934,C1206; tolerance: 5
C48-C61 = CAP: User Part Number: UPN; Tolerance: 10; alternate symbols: (C0603); part number: CAP_SM-0.1UF,50V,10,E030853,C0603; tolerance: 10
C62-C75 = CAP: User Part Number: UPN; Tolerance: 10; alternate symbols: (C0603); part number: CAP_SM-0.1UF,25V,10,E013746,C0603; tolerance: 10
C76 C78 C79 C82 = CAP: User Part Number: UPN; Tolerance: 5; alternate symbols: (C0402); part number: CAP_SM-15PF,50V,5,E035213,C0402; tolerance: 5
C77 C80 C81 C83 = CAP: User Part Number: UPN; Tolerance: 5; alternate symbols: (C0402); part number: CAP_SM-18PF,50V,5,E007476,C0402; tolerance: 5
C87 = CAP: User Part Number: UPN; Tolerance: 10; alternate symbols: (C0603); part number: CAP_SM-39PF,100V,10,E061747,C0603; tolerance: 10
C88 = CAP: Tolerance: 5; User Part Number: UPN; alternate symbols: (C1206H37); part number: CAP_SM-100PF,100V,5,E031046,C1206H37; tolerance: 5
C89-C92 = CAP: Tolerance: 5; User Part Number: UPN; alternate symbols: (C1206H71); part number: CAP_SM-2200PF,630V,5,E061748,C1206H71; tolerance: 5
C93 = CAP: User Part Number: UPN; Tolerance: 5; alternate symbols: (C0603); part number: CAP_SM-15PF,100V,5,E025452,C0603; tolerance: 5
C101 C102 = CAP: User Part Number: UPN; Tolerance: 5; alternate symbols: (C0805); part number: CAP_SM-100PF,100V,5,E000465,C0805; tolerance: 5
CM1 CM2 = FLTR4P_V7: User Part Number: UPN; Tolerance: N/A; alternate symbols: (FL1812); part number: FLTR4P_V7_SM-2800 OHMS,E015947,FL1812; tolerance: N/A
D3-D8 D11-D16 D18-D25 = DIOTVS2P_V4: Tolerance: N/A; User Part Number: UPN; alternate symbols: (SOD323_B); part number: DIOTVS2P_V4_SM-SP4021-01FTG,5V,N/A,E061749,SOD323_B; tolerance: N/A
D9 D10 = DIOTVS: User Part Number: UPN; Tolerance: N/A; alternate symbols: (SOD523H26); part number: DIOTVS_SM-PESD3V3U1UB,115,3.3V,N/A,E061833,SOD523H26; tolerance: N/A
D26 D28 D30 D31 = DIOSCHOTTKY: User Part Number: UPN; Tolerance: N/A; alternate symbols: (POWERDI123); part number: DIOSCHOTTKY_SM-DFLS1100-7,100V,N/A,E029142,POWERDI123; tolerance: N/A
D29 D32-D34 = DIOTVS3P_V6: User Part Number: UPN; Tolerance: N/A; alternate symbols: (SOT23_B); part number: DIOTVS3P_V6_SM-SESDONCAN1LT1G,24V,N/A,E061834,SOT23_B; tolerance: N/A
D40 = DIO: Tolerance: N/A; User Part Number: UPN; alternate symbols: (SOD323); part number: DIO_SM-BAT20J,23V,N/A,E001149,SOD323; tolerance: N/A
GP/AUX0-GP/AUX5 RXN1 RXN2 TXN1 TXN2 = CNTP1P: Tolerance: N/A; User Part Number: UPN; alternate symbols: (CNKEY5001TP); part number: CNTP1P_TH-BLK,E005347,CNKEY5001TP; tolerance: N/A
J1-J4 = CN16P: User Part Number: UPN; Tolerance: N/A; alternate symbols: (CNHDR1X16H335); part number: CN16P_TH-TSW-116-07-G-S,E058682,CNHDR1X16H335; tolerance: N/A
J5 = CN24P_ODD_EVEN: User Part Number: UPN; Tolerance: N/A; alternate symbols: (CNTHMHDR2X12L1200W200H343); part number: CN24P_ODD_EVEN_TH-PEC12DAAN,E061999,CNTHMHDR2X12L1200W200H343; tolerance: N/A
J6 = CN30P_ODD_EVEN_V2: Tolerance: N/A; User Part Number: UPN; alternate symbols: (CNTHMHDR2X15L1500W200H330); part number: CN30P_ODD_EVEN_V2_TH-PBC15DAAN,E051314,CNTHMHDR2X15L1500W200H330; tolerance: N/A
J7 = CN18P_ODD_EVEN_2GND: User Part Number: UPN; Tolerance: N/A; alternate symbols: (CNMOLEX5031541890); part number: CN18P_ODD_EVEN_2GND_SM-5031541890,E062000,CNMOLEX5031541890; tolerance: N/A
J8 = CN4P: User Part Number: UPN; Tolerance: N/A; alternate symbols: (CNSAMTECSSW-104-XX-X-S); part number: CN4P_TH-SSW-104-01-G-S,E025252,CNSAMTECSSW-104-XX-X-S; tolerance: N/A
L1-L4 = FERRITE: User Part Number: UPN; Tolerance: 25; alternate symbols: (L0805); part number: FERRITE_SM-600OHM AT 100MEGHZ,25,E040314,L0805; tolerance: 25
MINIQ1 = CN16P_ODD_EVEN: User Part Number: UPN; Tolerance: N/A; alternate symbols: (CNTHMHDR2X8L800W200H343_OE); part number: CN16P_ODD_EVEN_TH-PEC08DAAN,E035714,CNTHMHDR2X8L800W200H343_OE; tolerance: N/A
MINIQ2 = CN8P_A: User Part Number: UPN; Tolerance: N/A; alternate symbols: (CNSAMTECSSW-108-01-G-S); part number: CN8P_A_TH-SSW-108-01-G-S,E019099,CNSAMTECSSW-108-01-G-S; tolerance: N/A
Q1 Q2 = TRANPNP_DUAL: User Part Number: UPN; Tolerance: N/A; alternate symbols: (SOT363-3); part number: TRANPNP_DUAL_SM-BC857BS-7-F,E061835,SOT363-3; tolerance: N/A
R1-R4 R13-R16 R23 R24 R26 R136 R141 R143-R145 R148 = RES: User Part Number: UPN; Tolerance: JUMPER; alternate symbols: (R0603); part number: RES_SM-0,E034483,1/10W,JUMPER,R0603; tolerance: JUMPER
R5-R8 = RES: User Part Number: UPN; Tolerance: JUMPER; alternate symbols: (R0603); part number: RES_SM-0,E027148,1/4W,JUMPER,R0603; tolerance: JUMPER
R9 R10 R114 R115 R122-R128 R132-R134 R142 R146 R147 R150-R152 R154 = RES: User Part Number: UPN; Tolerance: 1; alternate symbols: (R0603); part number: RES_SM-10K,E060184,1/10W,1,R0603; tolerance: 1
R11 = RES: User Part Number: UPN; Tolerance: JUMPER; alternate symbols: (R0603); part number: RES_SM-0,E054377,1/10W,JUMPER,R0603; tolerance: JUMPER
R12 = RES: User Part Number: UPN; Tolerance: 1; alternate symbols: (R0603); part number: RES_SM-100K,E056988,1/10W,1,R0603; tolerance: 1
R17 = RES: Tolerance: 1; User Part Number: UPN; alternate symbols: (R1206-2); part number: RES_SM-100,E040377,1/2W,1,R1206-2; tolerance: 1
R18 = RES: User Part Number: UPN; Tolerance: 0.1; alternate symbols: (R0603); part number: RES_SM-1.02K,E061839,1/10W,0.1,R0603; tolerance: 0.1
R19 = RES: User Part Number: UPN; Tolerance: 1; alternate symbols: (R0603); part number: RES_SM-10,E049770,1/4W,1,R0603; tolerance: 1
R20 R27 R183 R184 = RES: User Part Number: UPN; Tolerance: 1; alternate symbols: (R0805); part number: RES_SM-0,E059953,1/8W,1,R0805; tolerance: 1
R21 R25 R29 R33 R35-R74 R77 = RES: Tolerance: 5; User Part Number: UPN; alternate symbols: (R1210); part number: RES_SM-22,E013618,1/2W,5,R1210; tolerance: 5
R22 = RES: User Part Number: UPN; Tolerance: 5; alternate symbols: (R0603); part number: RES_SM-100K,E060648,1/10W,5,R0603; tolerance: 5
R28 R30 R31 R185 R186 = RES: User Part Number: UPN; Tolerance: JUMPER; alternate symbols: (R0603); part number: RES_SM-0,E060257,1/4W,JUMPER,R0603; tolerance: JUMPER
R32 R34 = RES: User Part Number: UPN; Tolerance: N/A; alternate symbols: (R0805); part number: RES_SM-0,E004449,1/8W,N/A,R0805; tolerance: N/A
R81-R95 = RES: User Part Number: UPN; Tolerance: 1; alternate symbols: (R0603); part number: RES_SM-1K,E029591,1/10W,1,R0603; tolerance: 1
R96-R109 = RES: User Part Number: UPN; Tolerance: 1; alternate symbols: (R0603); part number: RES_SM-2K,E003711,1/10W,1,R0603; tolerance: 1
R110 R155 R161 R168 R169 = RES: User Part Number: UPN; Tolerance: 5; alternate symbols: (R0603); part number: RES_SM-100K,E042738,1/10W,5,R0603; tolerance: 5
R111 R112 = RES: User Part Number: UPN; Tolerance: 1; alternate symbols: (R0805); part number: RES_SM-360,E062002,1/8W,1,R0805; tolerance: 1
R113 = RES: User Part Number: UPN; Tolerance: 5; alternate symbols: (R0603); part number: RES_SM-1K,E042785,1/10W,5,R0603; tolerance: 5
R116-R121 = RES: User Part Number: UPN; Tolerance: 1; alternate symbols: (R0603); part number: RES_SM-1K,E015180,1/3W,1,R0603; tolerance: 1
R129 R130 R138 R140 R179-R182 R187 = RES: User Part Number: UPN; Tolerance: 5; alternate symbols: (R1206); part number: RES_SM-0,E010093,1/4W,5,R1206; tolerance: 5
R131 = RES: User Part Number: UPN; Tolerance: 1; alternate symbols: (R0603); part number: RES_SM-10K,E003671,1/10W,1,R0603; tolerance: 1
R137 R139 = RES: User Part Number: UPN; Tolerance: 1; alternate symbols: (R0603); part number: RES_SM-15K,E044558,1/10W,1,R0603; tolerance: 1
R157-R160 = RES: User Part Number: UPN; Tolerance: 1; alternate symbols: (R0805); part number: RES_SM-49.9,E003412,1/8W,1,R0805; tolerance: 1
R162 R164 R172 R173 = RES: User Part Number: UPN; Tolerance: 1; alternate symbols: (R1206); part number: RES_SM-1.5K,E031520,1/4W,1,R1206; tolerance: 1
SHDNL_SEL = CN3P: Tolerance: N/A; User Part Number: UPN; alternate symbols: (CN1X3H159); part number: CN3P_TH-FTS-103-01-F-S,E021702,CN1X3H159; tolerance: N/A
SW1 SW2 = SWITCH8_V2: User Part Number: UPN; Tolerance: N/A; alternate symbols: (SWDIP16); part number: SWITCH8_V2_TH-ADE0804,E004556,SWDIP16; tolerance: N/A
THERM1-THERM6 = CN2P: User Part Number: UPN; Tolerance: N/A; alternate symbols: (CNHDR1X2H408); part number: CN2P_TH-3-644456-2,E024442,CNHDR1X2H408; tolerance: N/A
U1 = ADES1754XXX: Tolerance: N/A; User Part Number: UPN; alternate symbols: (QFP64_10X10); part number: ADES1754XXX_SM-ADES1754GCB/V+,E061592,QFP64_10X10; tolerance: N/A
U2 = ICMAX337XEEUD: Tolerance: N/A; User Part Number: UPN; alternate symbols: (TSSOP14); part number: ICMAX337XEEUD_SM-MAX3378EEUD+,E013315,TSSOP14; tolerance: N/A
U3 = ICAT24C0XC: Tolerance: N/A; User Part Number: UPN; alternate symbols: (SO8); part number: ICAT24C0XC_SM-AT24CS08-SSHM-T,E062003,SO8; tolerance: N/A
U4 = ADMAX3390E: Tolerance: N/A; User Part Number: UPN; alternate symbols: (TSSOP14); part number: ADMAX3390E_SM-MAX3390EEUD+,E055428,TSSOP14; tolerance: N/A
U5 = TRANOPTO6P_V2: User Part Number: UPN; Tolerance: N/A; alternate symbols: (SO6_3_84X7_5); part number: TRANOPTO6P_V2_SM-TLP2770(TP,E,E062005,SO6_3_84X7_5; tolerance: N/A

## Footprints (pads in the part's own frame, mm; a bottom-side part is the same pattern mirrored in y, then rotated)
C0402
  rect 0.584x0.66 smd: 1(-0.5,0) 2(0.5,0)
C0603
  rect 0.762x0.889 smd: 1(-0.7,0) 2(0.7,0)
C0603#2
  rect 0.94x0.991 smd: 1(-0.8,0) 2(0.8,0)
C0805
  rect 1.143x1.448 smd: 1(-0.9,0) 2(0.9,0)
C0805H53
  rect 1.295x1.6 smd: 1(-0.953,0) 2(0.953,0)
C0805H60
  rect 1.295x1.6 smd: 1(-0.953,0) 2(0.953,0)
C1206
  rect 1.143x1.803 smd: 1(-1.5,0) 2(1.5,0)
C1206H37
  rect 1.6x2.007 smd: 1(-1.397,0) 2(1.397,0)
C1206H71
  rect 1.6x2.007 smd: 1(-1.397,0) 2(1.397,0)
C1210H95
  rect 1.575x2.692 smd: 1(-1.397,0) 2(1.397,0)
CN1X3H159
  oval 1.016x1.27 hole 0.762: 1(0,0) 2(1.27,0) 3(2.54,0)
CNHDR1X2H408
  rect 1.651x1.651 hole 1.143: 1(0,0)
  round 1.651 hole 1.143: 2(2.54,0)
CNHDR1X16H335
  rect 1.651x1.651 hole 1.143: 1(0,0)
  round 1.651 hole 1.143: 2(2.54,0) 3(5.08,0) 4(7.62,0) 5(10.16,0) 6(12.7,0) 7(15.24,0) 8(17.78,0) 9(20.32,0) 10(22.86,0) 11(25.4,0) 12(27.94,0) 13(30.48,0) 14(33.02,0) 15(35.56,0) 16(38.1,0)
CNKEY5001TP
  round 1.524 hole 1.016: 1(0,0)
CNMOLEX502584-0270
  rect 0.787x2.388 smd: 1(-0.75,-3.788) 2(0.75,-3.788)
  rect 1.803x3.302 smd: GND1(-3.352,1.255) GND2(3.352,1.255)
CNMOLEX5031541890
  rect 0.787x2.438 smd: 1(6,-4.7) 2(6,4.7) 3(4.5,-4.7) 4(4.5,4.7) 5(3,-4.7) 6(3,4.7) 7(1.5,-4.7) 8(1.5,4.7) 9(0,-4.7) 10(0,4.7) 11(-1.5,-4.7) 12(-1.5,4.7) 13(-3,-4.7) 14(-3,4.7) 15(-4.5,-4.7) 16(-4.5,4.7) 17(-6,-4.7) 18(-6,4.7)
  rect 1.803x5.055 smd: GND1(-8.53,1.1) GND2(8.53,1.1)
CNSAMTECSSW-104-XX-X-S
  rect 1.651x1.651 hole 1.143: 1(0,0)
  round 1.651 hole 1.143: 2(2.54,0) 3(5.08,0) 4(7.62,0)
CNSAMTECSSW-108-01-G-S
  rect 1.651x1.651 hole 1.143: 1(0,0)
  round 1.651 hole 1.143: 2(2.54,0) 3(5.08,0) 4(7.62,0) 5(10.16,0) 6(12.7,0) 7(15.24,0) 8(17.78,0)
CNSULLINSPEC02SAAN
  round 1.524 hole 1.016: 1(0,0) 2(2.54,0)
CNTHMHDR2X8L800W200H343_OE
  rect 1.651x1.651 hole 1.143: 1(0,0)
  round 1.651 hole 1.143: 2(0,2.54) 3(2.54,0) 4(2.54,2.54) 5(5.08,0) 6(5.08,2.54) 7(7.62,0) 8(7.62,2.54) 9(10.16,0) 10(10.16,2.54) 11(12.7,0) 12(12.7,2.54) 13(15.24,0) 14(15.24,2.54) 15(17.78,0) 16(17.78,2.54)
CNTHMHDR2X12L1200W200H343
  rect 1.651x1.651 hole 1.143: 1(0,0)
  round 1.651 hole 1.143: 2(0,2.54) 3(2.54,0) 4(2.54,2.54) 5(5.08,0) 6(5.08,2.54) 7(7.62,0) 8(7.62,2.54) 9(10.16,0) 10(10.16,2.54) 11(12.7,0) 12(12.7,2.54) 13(15.24,0) 14(15.24,2.54) 15(17.78,0) 16(17.78,2.54) 17(20.32,0) 18(20.32,2.54) 19(22.86,0) 20(22.86,2.54) 21(25.4,0) 22(25.4,2.54) 23(27.94,0) 24(27.94,2.54)
CNTHMHDR2X15L1500W200H330
  rect 1.651x1.651 hole 1.143: 1(0,0)
  round 1.651 hole 1.143: 2(0,2.54) 3(2.54,0) 4(2.54,2.54) 5(5.08,0) 6(5.08,2.54) 7(7.62,0) 8(7.62,2.54) 9(10.16,0) 10(10.16,2.54) 11(12.7,0) 12(12.7,2.54) 13(15.24,0) 14(15.24,2.54) 15(17.78,0) 16(17.78,2.54) 17(20.32,0) 18(20.32,2.54) 19(22.86,0) 20(22.86,2.54) 21(25.4,0) 22(25.4,2.54) 23(27.94,0) 24(27.94,2.54) 25(30.48,0) 26(30.48,2.54) 27(33.02,0) 28(33.02,2.54) 29(35.56,0) 30(35.56,2.54)
CNWEICO9020
  oval 5.08x1.905 hole 1: 1(0,0)
FL1812
  rect 1.346x0.889 smd: 1(-2.273,1.245) 2(-2.273,-1.245) 3(2.273,-1.245) 4(2.273,1.245)
L0805
  rect 1.194x1.448 smd: 1(-0.85,0) 2(0.85,0)
POWERDI123
  rect 0.889x1.397 smd: A(1.606,0)
  rect 2.21x1.397 smd: C(-0.945,0)
QFP64_10X10
  rect 0.305x1.27 smd: 1(-3.75,-5.635) 2(-3.25,-5.635) 3(-2.75,-5.635) 4(-2.25,-5.635) 5(-1.75,-5.635) 6(-1.25,-5.635) 7(-0.75,-5.635) 8(-0.25,-5.635) 9(0.25,-5.635) 10(0.75,-5.635) 11(1.25,-5.635) 12(1.75,-5.635) 13(2.25,-5.635) 14(2.75,-5.635) 15(3.25,-5.635) 16(3.75,-5.635) 33(3.75,5.635) 34(3.25,5.635) 35(2.75,5.635) 36(2.25,5.635) 37(1.75,5.635) 38(1.25,5.635) 39(0.75,5.635) 40(0.25,5.635) 41(-0.25,5.635) 42(-0.75,5.635) 43(-1.25,5.635) 44(-1.75,5.635) 45(-2.25,5.635) 46(-2.75,5.635) 47(-3.25,5.635) 48(-3.75,5.635)
  rect 1.27x0.305 smd: 17(5.635,-3.75) 18(5.635,-3.25) 19(5.635,-2.75) 20(5.635,-2.25) 21(5.635,-1.75) 22(5.635,-1.25) 23(5.635,-0.75) 24(5.635,-0.25) 25(5.635,0.25) 26(5.635,0.75) 27(5.635,1.25) 28(5.635,1.75) 29(5.635,2.25) 30(5.635,2.75) 31(5.635,3.25) 32(5.635,3.75) 49(-5.635,3.75) 50(-5.635,3.25) 51(-5.635,2.75) 52(-5.635,2.25) 53(-5.635,1.75) 54(-5.635,1.25) 55(-5.635,0.75) 56(-5.635,0.25) 57(-5.635,-0.25) 58(-5.635,-0.75) 59(-5.635,-1.25) 60(-5.635,-1.75) 61(-5.635,-2.25) 62(-5.635,-2.75) 63(-5.635,-3.25) 64(-5.635,-3.75)
R0603
  rect 0.787x0.991 smd: 1(-0.85,0) 2(0.85,0)
R0805
  rect 1.041x1.397 smd: 1(-0.95,0) 2(0.95,0)
R1206
  rect 1.041x1.753 smd: 1(-1.5,0) 2(1.5,0)
R1206-2
  rect 1.397x1.803 smd: 1(-1.298,0) 2(1.298,0)
R1210
  rect 1.575x2.692 smd: 1(-1.397,0) 2(1.397,0)
SO6_3_84X7_5
  rect 0.635x1.702 smd: 1(-1.27,-4.601) 2(0,-4.601) 3(1.27,-4.601) 4(1.27,4.601) 5(0,4.601) 6(-1.27,4.601)
SO8
  rect 0.61x2.184 smd: 1(-1.905,-2.54) 2(-0.635,-2.54) 3(0.635,-2.54) 4(1.905,-2.54) 5(1.905,2.54) 6(0.635,2.54) 7(-0.635,2.54) 8(-1.905,2.54)
SOD323
  rect 1.27x0.889 smd: A(1.143,0) C(-1.143,0)
SOD323_B
  rect 0.889x0.508 smd: 1(-1.3,0) 2(1.3,0)
SOD523H26
  rect 0.787x0.61 smd: A(0.55,0) C(-0.55,0)
SOT23_B
  rect 0.61x1.041 smd: 1(-0.958,-1.15) 2(0.958,-1.15) 3(0,1.15)
SOT363-3
  rect 0.432x0.61 smd: 1(-0.65,-0.95) 2(0,-0.95) 3(0.65,-0.95) 4(0.65,0.95) 5(0,0.95) 6(-0.65,0.95)
SWDIP16
  rect 1.524x1.524 hole 1.016: 1(0,0)
  round 1.524 hole 1.016: 2(2.54,0) 3(5.08,0) 4(7.62,0) 5(10.16,0) 6(12.7,0) 7(15.24,0) 8(17.78,0) 9(17.78,7.62) 10(15.24,7.62) 11(12.7,7.62) 12(10.16,7.62) 13(7.62,7.62) 14(5.08,7.62) 15(2.54,7.62) 16(0,7.62)
TSSOP14
  rect 0.432x1.778 smd: 1(-1.95,-2.92) 2(-1.3,-2.92) 3(-0.65,-2.92) 4(0,-2.92) 5(0.65,-2.92) 6(1.3,-2.92) 7(1.95,-2.92) 8(1.95,2.92) 9(1.3,2.92) 10(0.65,2.92) 11(0,2.92) 12(-0.65,2.92) 13(-1.3,2.92) 14(-1.95,2.92)
unnamed#2
  round 1.016 smd: (0,0)

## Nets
3.3V: MINIQ1.15 R132.1 U2.1(VL) U4.1(VL)
5.0V: J8.1 R24.2(N2) R34.2(N2)
GND_POWER: ALARM_IN_UP.GND1 ALARM_IN_UP.GND2(N4) ALARM_OUT_LP.GND1 ALARM_OUT_LP.GND2(N4) B0P-.1 C2.2(N2) C3.2(N2) C4.2(N2) C5.2(N2) C7.2(N2) C8.2(N2) C9.2(N2) C10.2(N2) C11.2(N2) C12.2(N2) C13.2(N2) C14.2(N2) C15.2(N2) C16.2(N2) C17.2(N2) C18.2(N2) C19.2(N2) C20.2(N2) C21.2(N2) C22.2(N2) C23.2(N2) C24.2(N2) C25.2(N2) C26.2(N2) C27.2(N2) C28.2(N2) C29.2(N2) C30.2(N2) C31.2(N2) C32.2(N2) C33.2(N2) C34.1 C35.1 C36.1 C37.1 C38.1 C39.1 C40.1 C41.1 C42.1 C43.1 C44.1 C45.1 C46.1 C47.1 C76.2(N2) C77.2(N2) C78.2(N2) C79.2(N2) C80.2(N2) C81.2(N2) C82.2(N2) C83.2(N2) C84.2(N2) C85.2(N2) C87.2(N2) C93.2(N2) C100.2(N2) C101.2(N2) C102.1 C104.2(N2) C105.2(N2) C106.2(N2) C107.2(N2) C108.2(N2) C109.2(N2) CURRENTSENSE.GND1 CURRENTSENSE.GND2(N4) D3.2(N2) D4.2(N2) D5.2(N2) D6.2(N2) D7.2(N2) D8.2(N2) D9.A(P) D10.A(P) D11.2(N2) D12.2(N2) D13.2(N2) D14.2(N2) D15.2(N2) D16.2(N2) D18.2(N2) D19.2(N2) D20.2(N2) D21.2(N2) D22.2(N2) D23.2(N2) D24.2(N2) D25.2(N2) D26.A(P) D28.A(P) D29.3(N3) D30.A(P) D31.A(P) D32.3(N3) D33.3(N3) D34.3(N3) GND_A.1(N1) GND_A1.1(N1) GND_A2.1(N1) GND_A3.1(N1) GPIO_AUX0.2 GPIO_AUX0.GND1 GPIO_AUX0.GND2(N4) GPIO_AUX1.2 GPIO_AUX1.GND1 GPIO_AUX1.GND2(N4) GPIO_AUX2.2 GPIO_AUX2.GND1 GPIO_AUX2.GND2(N4) GPIO_AUX3.2 GPIO_AUX3.GND1 GPIO_AUX3.GND2(N4) GPIO_AUX4.2 GPIO_AUX4.GND1 GPIO_AUX4.GND2(N4) GPIO_AUX5.2 GPIO_AUX5.GND1 GPIO_AUX5.GND2(N4) J1.2 J1.6 J1.8 J1.14 J2.12 J5.1 J5.2 J5.7 J5.8 J5.13 J5.14 J5.19 J5.20 J5.23 J5.24 J7.1 J7.GND1 J7.GND2 J8.3 MINIQ1.1 MINIQ2.6 PACK-.1(N1) Q1.3 Q1.6 Q2.3 Q2.6 R10.1 R12.1 R28.2(N2) R30.1 R31.2(N2) R110.2(N2) R112.2(N2) R134.2(N2) R139.2(N2) R147.2(N2) R150.2(N2) R152.2(N2) R155.2(N2) R161.2(N2) R168.2(N2) R169.2(N2) RXLP_CONN.GND1 RXLP_CONN.GND2(N4) RXUP_CONN.GND1 RXUP_CONN.GND2(N4) TXLP_CONN.GND1 TXLP_CONN.GND2(N4) TXUP_CONN.GND1 TXUP_CONN.GND2(N4) U1.2 U1.6 U1.8 U1.14 U1.28 U2.7 U3.4 U3.7(WP) U4.7 U5.4
VDDL1: C4.1 J1.5 R11.2(N2) U1.5 VDDL1.1(N1)
VDDL2/VDDL3: C5.1 C7.1 J1.11 J2.3 Q1.2 Q1.5 Q2.2 Q2.5 R26.2(N2) R32.2(N2) R34.1 R114.1 R133.1 R142.1 R146.1 R151.1 R154.1 U1.11(VDDL3) U1.19 U2.14 U4.14 U5.6(VDD) VDDL2/3.1(N1)
ALERTIN: ALERTIN.1(N1) C87.1 J1.7 OPTO_OUT.1(N1) R12.2(N2) R110.1 R113.2(N2) U1.7
ALERTOUT: ALERTOUT.1(N1) J2.4 R136.2(N2) R141.1 U1.20
AUXGND: AUXGND.1(N1) J2.9(N9) R28.1 U1.25
BAT0: B0P-.2(N2) B1B0.1 BAT0.1(N1) J6.1 J6.2 J7.2 R54.1 R74.1 R77.1 R83.1 SW2.16
BAT1: B1B0.2(N2) B2B1.1 BAT1.1(N1) C47.2(N2) J6.3 J6.4 J7.3 R52.1 R70.1 R73.1 R82.1 SW2.15
BAT2: B2B1.2(N2) B3B2.1 BAT2.1(N1) C46.2(N2) J6.5 J6.6 J7.4 R51.1 R68.1 R69.1 R81.1 SW2.14
BAT3: B3B2.2(N2) B4B3.1 BAT3.1(N1) C45.2(N2) J6.7 J6.8 J7.5 R50.1 R65.1 R67.1 R87.1 SW2.13
BAT4: B4B3.2(N2) B5B4.1 BAT4.1(N1) C44.2(N2) J6.9 J6.10 J7.6 R48.1 R61.1 R66.1 R86.1 SW2.12
BAT5: B5B4.2(N2) B6B5.1 BAT5.1(N1) C43.2(N2) J6.11 J6.12 J7.7 R47.1 R57.1 R64.1 R85.1 SW2.11
BAT6: B6B5.2(N2) B7B6.1 BAT6.1(N1) C42.2(N2) J6.13 J6.14 J7.8 R46.1 R53.1 R72.1 R84.1 SW2.10
BAT7: B7B6.2(N2) B8B7.1 BAT7.1(N1) C41.2(N2) J6.15 J6.16 J7.9 R44.1 R49.1 R63.1 R89.1 SW2.9(N9)
BAT8: B8B7.2(N2) B9B8.1 BAT8.1(N1) C40.2(N2) J6.17 J6.18(N9) J7.10 R43.1 R45.1 R62.1 R88.1 SW1.16
BAT9: B9B8.2(N2) B10B9.1 BAT9.1(N1) C39.2(N2) J6.19 J6.20 J7.11 R41.1 R42.1 R71.1 R90.1 SW1.15
BAT10: B10B9.2(N2) B11B10.1 BAT10.1(N1) C38.2(N2) J6.21 J6.22 J7.12 R37.1 R40.1 R60.1 R95.1 SW1.14
BAT11: B11B10.2(N2) B12B11.1 BAT11.1(N1) C37.2(N2) J6.23 J6.24 J7.13 R33.1 R39.1 R59.1 R94.1 SW1.13
BAT12: B12B11.2(N2) B13B12.1 BAT12.1(N1) C36.2(N2) J6.25 J6.26 J7.14 R29.1 R38.1 R55.1 R93.1 SW1.12
BAT13: B13B12.2(N2) B14B13.1 BAT13.1(N1) C35.2(N2) J6.27 J6.28 J7.15 R25.1 R36.1 R58.1 R92.1 SW1.11
BAT14: B14B13.2(N2) BAT14.1(N1) C34.2(N2) J6.29 J6.30 J7.16 P+B14.1 R18.1 R21.1 R35.1 R56.1 R91.1 R187.2(N2) SW1.10
C0: C61.2(N2) J2.14 R83.2(N2) U1.30
C1: C60.2(N2) C61.1 C84.1 J2.16 R82.2(N2) U1.32
C2: C33.1 C59.2(N2) C60.1 J3.2 R81.2(N2) U1.34
C3: C32.1 C58.2(N2) C59.1 J3.4 R87.2(N2) U1.36
C4: C31.1 C57.2(N2) C58.1 J3.6 R86.2(N2) U1.38
C5: C30.1 C56.2(N2) C57.1 J3.8 R85.2(N2) U1.40
C6: C29.1 C55.2(N2) C56.1 J3.10 R84.2(N2) U1.42
C7: C28.1 C54.2(N2) C55.1 J3.12 R89.2(N2) U1.44
C8: C27.1 C53.2(N2) C54.1 J3.14 R88.2(N2) U1.46
C9: C26.1 C52.2(N2) C53.1 J3.16 R90.2(N2) U1.48
C10: C25.1 C51.2(N2) C52.1 J4.2 R95.2(N2) U1.50
C11: C24.1 C50.2(N2) C51.1 J4.4 R94.2(N2) U1.52
C12: C23.1 C49.2(N2) C50.1 J4.6 R93.2(N2) U1.54
C13: C22.1 C48.2(N2) C49.1 J4.8 R92.2(N2) U1.56
C14: C20.1 C48.1 J4.10 R91.2(N2) U1.58
CPN: C1.1 CPN.1(N1) J4.14 U1.62
CPP: C1.2(N2) CPP.1(N1) J4.15 U1.63
CS0: D13.1 MINIQ1.9 U2.3
CS0_HV: R1.1 U2.12
CS1: D19.1 MINIQ1.14
CS2: D18.1 MINIQ1.16(N8)
DCIN: C6.1 C18.1 C19.1 D40.A(P) DCIN.1(N1) J4.13 R17.2(N2) U1.61
GPIO0/AUXIN0: C8.1 J2.5 J5.4 R116.2(N2) R148.2(N2) U1.21
GPIO0/AUXIN0_OUT: C106.1 D5.1 GP/AUX0.1(N1) GPIO_AUX0.1 J5.3 R116.1 THERM1.1
GPIO1/AUXIN1: C9.1 J2.6 J5.6 R117.2(N2) R143.1 U1.22
GPIO1/AUXIN1_OUT: C107.1 D6.1 GP/AUX1.1(N1) GPIO_AUX1.1 J5.5 R117.1 THERM2.1
GPIO2/AUXIN2: C10.1 J2.7 J5.10 R121.2(N2) U1.23
GPIO2/AUXIN2_OUT: C108.1 D7.1 GP/AUX2.1(N1) GPIO_AUX2.1 J5.9 R121.1 THERM3.1
GPIO3/AUXIN3: C11.1 C16.1 J2.8 J5.12 R118.2(N2) R137.1 U1.24
GPIO3/AUXIN3_OUT: C105.1 D8.1 GP/AUX3.1(N1) GPIO_AUX3.1 J5.11 R118.1 THERM4.1
GPIO4/AUXIN4: C12.1 C86.1 J2.10 J5.16 R119.2(N2) U1.26
GPIO4/AUXIN4_OUT: CURRENTSENSE.2 D4.1 J5.15 R119.1 R185.2(N2) THERM5.1
GPIO5/AUXIN5: C13.1 C86.2(N2) J2.11 J5.18(N9) R30.2(N2) R120.2(N2) U1.27
GPIO5/AUXIN5_OUT: CURRENTSENSE.1 D3.1 J5.17 R31.1 R120.1 R186.2(N2) THERM6.1
GPIO8: D15.1 MINIQ1.5
HV: D40.C HV.1(N1) J4.16 R19.2(N2) R23.2(N2) U1.64
INT2: D16.1 MINIQ1.3
MINIQ_SHDNL: D20.1 MINIQ1.12 SHDNL_SEL.1
PACK+: C100.1 J7.17 P+B14.2(N2) PACK+.1(N1) R17.1 R187.1
RXLN: C80.1 J2.2 R138.2(N2) RXLN.1(N1) U1.18
RXLP: C83.1 J2.1 R140.2(N2) RXLP.1(N1) U1.17
RXN1: C89.1 RXLP_CONN.1 RXN1.1(N1)
RXN2: C91.2(N2) RXN2.1(N1) RXUP_CONN.2
RXP1: C90.1 RXLP_CONN.2 RXP1.1(N1)
RXP2: C92.2(N2) RXP2.1(N1) RXUP_CONN.1
RXUN: C77.1 J1.12 R129.2(N2) RXUN.1(N1) U1.12
RXUP: C81.1 J1.13 R130.2(N2) RXUP.1(N1) U1.13
SCLK: D12.1 MINIQ1.11 U2.4
SCLK_HV: R3.1 U2.11
SDI: D14.1 MINIQ1.7 U2.2
SDI_HV: R2.1 U2.13
SDO: D11.1 MINIQ1.13 U2.5
SDO_HV: R4.1 U2.10
SHDNL: J1.1 R22.2(N2) SHDNL.1(N1) SHDNL_SEL.2
SW0: C75.2(N2) C85.1 J2.15 R54.2(N2) R74.2(N2) R77.2(N2) U1.31
SW1: C74.2(N2) C75.1 J3.1 R52.2(N2) R70.2(N2) R73.2(N2) U1.33
SW2: C73.2(N2) C74.1 J3.3 R51.2(N2) R68.2(N2) R69.2(N2) U1.35
SW3: C72.2(N2) C73.1 J3.5 R50.2(N2) R65.2(N2) R67.2(N2) U1.37
SW4: C71.2(N2) C72.1 J3.7 R48.2(N2) R61.2(N2) R66.2(N2) U1.39
SW5: C70.2(N2) C71.1 J3.9(N9) R47.2(N2) R57.2(N2) R64.2(N2) U1.41
SW6: C69.2(N2) C70.1 J3.11 R46.2(N2) R53.2(N2) R72.2(N2) U1.43
SW7: C68.2(N2) C69.1 J3.13 R44.2(N2) R49.2(N2) R63.2(N2) U1.45
SW8: C67.2(N2) C68.1 J3.15 R43.2(N2) R45.2(N2) R62.2(N2) U1.47
SW9: C66.2(N2) C67.1 J4.1 R41.2(N2) R42.2(N2) R71.2(N2) U1.49
SW10: C65.2(N2) C66.1 J4.3 R37.2(N2) R40.2(N2) R60.2(N2) U1.51
SW11: C64.2(N2) C65.1 J4.5 R33.2(N2) R39.2(N2) R59.2(N2) U1.53
SW12: C63.2(N2) C64.1 J4.7 R29.2(N2) R38.2(N2) R55.2(N2) U1.55
SW13: C62.2(N2) C63.1 J4.9(N9) R25.2(N2) R36.2(N2) R58.2(N2) U1.57
SW14: C62.1 J4.11 R21.2(N2) R35.2(N2) R56.2(N2) U1.59
THERM: C14.1 J2.13 J5.21 J5.22 R122.1 R123.1 R124.1 R126.1 R127.1 R128.1 THERM.1(N1) U1.29
TXLN: D31.C R14.1 R150.1 R151.2(N2) R157.2(N2) TXLN.1(N1)
TXLN_SDI: J1.16 Q1.1 R2.2(N2) R8.1 R14.2(N2)
TXLNSDI: C82.1 R8.2(N2) U1.16
TXLP: D28.C R16.1 R152.1 R154.2(N2) R160.2(N2) TXLP.1(N1)
TXLP_SDO: J1.15 Q1.4(E2) R4.2(N2) R7.1 R16.2(N2)
TXLPSDO: C78.1 R7.2(N2) U1.15
TXN1: CM2.1 R20.1 TXLP_CONN.1 TXN1.1(N1)
TXN2: D33.2 L1.1 R179.2(N2)
TXP1: CM2.2 R27.1 TXLP_CONN.2 TXP1.1(N1)
TXP2: D33.1 L2.1 R180.2(N2)
TXUN: D30.C R15.1 R133.2(N2) R134.1 R158.2(N2) TXUN.1(N1)
TXUN_SCLK: J1.9(N9) Q2.1 R3.2(N2) R5.1 R15.2(N2)
TXUNSCLK: C76.1 R5.2(N2) U1.9
TXUP: D26.C R13.1 R146.2(N2) R147.1 R159.2(N2) TXUP.1(N1)
TXUP_CS0: J1.10 Q2.4(E2) R1.2(N2) R6.1 R13.2(N2)
TXUPCS0: C79.1 R6.2(N2) U1.10
UARTSEL: J1.4 R9.1 R10.2(N2) U1.4 UARTSEL.1(N1)
UNNAMED_4_ADES1754XXX_I843_SHDNL: C2.1 R22.1 U1.1
UNNAMED_4_CAP_I874_N2: C6.2(N2) R19.1
UNNAMED_7_CAP_I800_N1: ALARM_IN_UP.1 ALERTIN_N.1(N1) C88.1 U5.3
UNNAMED_7_CAP_I800_N2: ALARM_IN_UP.2 ALERTIN_P.1(N1) C88.2(N2) U5.1
UNNAMED_7_CAP_I813_N1: C93.1 R111.2(N2) R136.1
UNNAMED_7_CAP_I821_N1: C104.1 GP/AUX5.1(N1) GPIO_AUX5.1 R186.1
UNNAMED_7_CAP_I822_N1: C109.1 GP/AUX4.1(N1) GPIO_AUX4.1 R185.1
UNNAMED_7_CAP_I841_N1: C17.1 R137.2(N2) R139.1 R144.1 R145.1
UNNAMED_7_CAP_I843_N1: C91.1 R162.1
UNNAMED_7_CAP_I844_N1: C92.1 R164.1
UNNAMED_7_CAP_I847_N2: C89.2(N2) R172.1
UNNAMED_7_CAP_I848_N2: C90.2(N2) R173.1
UNNAMED_7_CN2P_I834_N2: R122.2(N2) THERM1.2(N2)
UNNAMED_7_CN2P_I835_N2: R123.2(N2) THERM2.2(N2)
UNNAMED_7_CN2P_I836_N2: R124.2(N2) THERM3.2(N2)
UNNAMED_7_CN2P_I837_N2: R126.2(N2) THERM4.2(N2)
UNNAMED_7_CN2P_I838_N2: R127.2(N2) THERM5.2(N2)
UNNAMED_7_CN2P_I839_N2: R128.2(N2) THERM6.2(N2)
UNNAMED_7_CN4P_I840_N2: J8.2 R144.2(N2)
UNNAMED_7_CN4P_I840_N4: J8.4(N4) R145.2(N2)
UNNAMED_7_CN18PODDEVEN2GND_I950_N9: J7.18(N9) R23.1
UNNAMED_7_DIOTVS3PV6_I845_N1: D29.1 R130.1 R161.1 R164.2(N2)
UNNAMED_7_DIOTVS3PV6_I845_N2: D29.2 R129.1 R155.1 R162.2(N2)
UNNAMED_7_DIOTVS3PV6_I846_N1: D32.1 R140.1 R169.1 R173.2(N2)
UNNAMED_7_DIOTVS3PV6_I846_N2: D32.2 R138.1 R168.1 R172.2(N2)
UNNAMED_7_DIOTVS_I814_N: ALARM_OUT_LP.2 D10.C R112.1
UNNAMED_7_DIOTVS_I815_N: ALARM_OUT_LP.1 D9.C R111.1
UNNAMED_7_ICAT24C0XC_I842_A2: R125.2(N2) U3.3
UNNAMED_7_ICAT24C0XC_I842_SCL: R115.2(N2) R143.2(N2) U3.6
UNNAMED_7_ICAT24C0XC_I842_SDA: R131.2(N2) R148.1 U3.5
UNNAMED_7_ICAT24C0XC_I842_VCC: R26.1 R115.1 R125.1 R131.1 U3.8
UNNAMED_7_RES_I895_N1: R96.1 SW1.7
UNNAMED_7_RES_I895_N2: R96.2(N2) R97.1 SW1.6
UNNAMED_7_RES_I896_N2: R97.2(N2) R98.1 SW1.5
UNNAMED_7_RES_I897_N2: R98.2(N2) R99.1 SW1.4
UNNAMED_7_RES_I898_N2: R99.2(N2) R100.1 SW1.3
UNNAMED_7_RES_I899_N2: R100.2(N2) R101.1 SW1.2
UNNAMED_7_RES_I901_N1: R101.2(N2) R102.1 SW1.1
UNNAMED_7_RES_I901_N2: R102.2(N2) R103.1 SW2.8
UNNAMED_7_RES_I902_N2: R103.2(N2) R104.1 SW2.7
UNNAMED_7_RES_I903_N2: R104.2(N2) R105.1 SW2.6
UNNAMED_7_RES_I905_N1: R105.2(N2) R106.1 SW2.5
UNNAMED_7_RES_I905_N2: R106.2(N2) R107.1 SW2.4
UNNAMED_7_RES_I907_N1: R107.2(N2) R108.1 SW2.3
UNNAMED_7_RES_I907_N2: R108.2(N2) R109.1 SW2.2
UNNAMED_7_RES_I908_N2: R109.2(N2) SW2.1
UNNAMED_7_RES_I921_N1: R113.1 U5.5
UNNAMED_8_ADMAX3390E_I407_3STATEN: R132.2(N2) U2.8 U4.8
UNNAMED_8_ADMAX3390E_I407_IVCC1: R141.2(N2) U4.13
UNNAMED_8_ADMAX3390E_I407_OVL1: D24.1 MINIQ1.4 R142.2(N2) U4.2
UNNAMED_8_CAP_I399_N1: C101.1 CM2.4(N4) R20.2(N2) R181.1
UNNAMED_8_CAP_I400_N2: C102.2(N2) CM2.3 R27.2(N2) R182.1
UNNAMED_8_CN2P2GND_I383_N1: CM1.1 R184.1 TXP2.1(N1) TXUP_CONN.1
UNNAMED_8_CN2P2GND_I383_N2: CM1.2 R183.1 TXN2.1(N1) TXUP_CONN.2
UNNAMED_8_CN8PA_I435_N7: MINIQ2.7 R24.1
UNNAMED_8_DIOTVS2PV4_I413_N1: D25.1 MINIQ1.2 R114.2(N2)
UNNAMED_8_DIOTVS2PV4_I415_N1: D23.1 MINIQ1.6
UNNAMED_8_DIOTVS2PV4_I416_N1: D22.1 MINIQ1.8
UNNAMED_8_DIOTVS2PV4_I417_N1: D21.1 MINIQ1.10
UNNAMED_8_DIOTVS3PV6_I401_N1: D34.1 L4.1 R182.2(N2)
UNNAMED_8_DIOTVS3PV6_I401_N2: D34.2 L3.1 R181.2(N2)
UNNAMED_8_FERRITE_I392_N2: L1.2(N2) R158.1
UNNAMED_8_FERRITE_I393_N2: L2.2(N2) R159.1
UNNAMED_8_FERRITE_I402_N2: L3.2(N2) R157.1
UNNAMED_8_FERRITE_I403_N2: L4.2(N2) R160.1
UNNAMED_8_FLTR4PV7_I388_N3: CM1.3 R179.1 R183.2(N2)
UNNAMED_8_FLTR4PV7_I388_N4: CM1.4(N4) R180.1 R184.2(N2)
VAA: C3.1 C15.1 J1.3 R9.2(N2) R11.1 R32.1 U1.3 VAA.1(N1)
VBLKP: C21.1 J4.12 R18.2(N2) U1.60 VBLK.1(N1)
